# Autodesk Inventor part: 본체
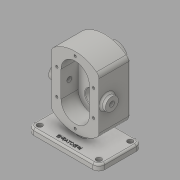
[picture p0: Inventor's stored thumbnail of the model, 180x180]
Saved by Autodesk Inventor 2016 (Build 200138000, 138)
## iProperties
Created: 2019-03
Part Number: 본체
Material: Generic
Document SubType Name: Modeling
Designer: Administrator
Density: 1 g/cm^3
Appearance: Default
Author: Administrator
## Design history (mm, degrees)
sketch "스케치1"
  geometry: L1 (60, -36.5)-(-60, -36.5); L2 (-60, -36.5)-(-60, 36.5); L3 (-60, 36.5)-(60, 36.5); L4 (60, 36.5)-(60, -36.5); L5 (60, -36.5)-(-60, 36.5); L6 (-60, -36.5)-(60, 36.5); 1 further point
  constraints: 12 end point, 2 midpoint, 2 parallel, 1 horizontal, 1 perpendicular
  dimensions: "d0" = 120 distance of L1.start L1.end; "d1" = 73 distance of L1.end L2.end
extrude "돌출1" new body sketch "스케치1" distance "d2" = 10; taper "d3" = 0 deg
fillet "모깎기1" dims "d4" = 10
sketch "스케치2"
  geometry: 1 further point
sketch "스케치3"
  geometry: L1 (50, 36.5)-(-50, 36.5) reference; L2 (0, 0)-(0, 36.5); L3 (-6, -6.5)-(6, -6.5); L4 (6, -6.5)-(6, 36.5); L5 (6, 36.5)-(-6, 36.5); L6 (-6, 36.5)-(-6, -6.5); 1 further point
  constraints: 10 end point, 3 midpoint, 2 parallel, 1 horizontal, 1 perpendicular
  dimensions: "d42" = 12 distance of L3.start L3.end; "d43" = 43 distance of L3.end L4.end
extrude "돌출2" join sketch "스케치3" distance "d44" = 78; taper "d45" = 0 deg
fillet "모깎기3" dims "d46" = 3
sketch "스케치4"
  geometry: L1 (10, 66)-(90, 66); L2 (90, 66)-(90, 110); L3 (90, 110)-(10, 110); L4 (10, 110)-(10, 66); L5 (56, 88)-(44, 88) reference; L6 (10, 66)-(90, 110); L7 (90, 66)-(10, 110); L8 (50, 0)-(50, 138); L9 (50, 138)-(61.235, 138); L10 (10, 110)-(10, 122.721); L11 (90, 110)-(90, 122.721); L12 (10, 66)-(-38.552, 66); L13 (90, 66)-(122.984, 66); A1 r 60 centre (50, 78) between (90, 122.721) and (10, 122.721); 1 further point
  constraints: 24 end point, 4 horizontal, 3 midpoint, 3 point on circle, 3 vertical, 2 parallel, 1 centre point, 1 perpendicular, 1 point on line, 1 tangent
  dimensions: "d47" = 44 distance of L1.end L2.end; "d48" = 80 distance of L2.end L3.end; "d49" = 138 distance of L8.start L8.end; "d51" = 60 radius of A1
extrude "돌출3" join sketch "스케치4" distance "d52" = 53; taper "d53" = 0 deg
node "작업 평면1"
sketch "스케치7"
  geometry: L1 (-50, 100)-(-50, 56); L2 (-50, 100)-(-50, 56); L3 (-74, 100)-(-74, 56); L4 (-26, 56)-(-26, 100); A1 r 60 centre (-50, 78) between (-10, 122.721) and (-90, 122.721) reference; A2 r 24 centre (-50, 100) between (-26, 100) and (-74, 100); A3 r 24 centre (-50, 56) between (-74, 56) and (-26, 56); 3 further points
  constraints: 10 end point, 4 point on circle, 4 tangent, 2 centre point, 2 midpoint, 2 vertical, 1 coincident, 1 parallel
  dimensions: "d55" = 44 distance of L1.start L1.end; "d56" = 24 radius of A2
extrude "돌출4" cut sketch "스케치7" distance "d57" = 29; taper "d58" = 0 deg
fillet "모깎기4" dims "d59" = 10
sketch "스케치8"
  geometry: L1 (90, 38)-(90, 118) reference; L2 (10, 38)-(10, 118) reference; L3 (44, 7)-(44, 18.301) reference; L4 (0, 7)-(44, 7) reference; L5 (0, 0)-(0, 7) reference; L6 (100, 0)-(0, 0) reference; L7 (100, 7)-(100, 0) reference; L8 (56, 7)-(100, 7) reference; L9 (56, 18.301)-(56, 7) reference; C1 r 19 at (50, 100); A1 r 10 centre (80, 38) between (86, 30) and (90, 38) reference; A2 r 10 centre (80, 118) between (90, 118) and (86, 126) reference; A3 r 60 centre (50, 78) between (86, 126) and (14, 126) reference; A4 r 10 centre (20, 118) between (14, 126) and (10, 118) reference; A5 r 10 centre (20, 38) between (10, 38) and (14, 30) reference; A6 r 60 centre (50, 78) between (14, 30) and (44, 18.301) reference; A7 r 60 centre (50, 78) between (56, 18.301) and (86, 30) reference; A8 r 24 centre (50, 100) between (74, 100) and (26, 100) reference; 1 further point
  constraints: 1 centre point, 1 coincident
  dimensions: "d60" = 38 diameter of C1
extrude "돌출5" join sketch "스케치8" distance "d61" = 17; taper "d62" = 0 deg
fillet "모깎기5" dims "d63" = 3
hole "구멍5" diameter "d66" = 17; stored, may be unused: countersink angle "d70" = 90 deg, drill point angle "d72" = 118 deg; dims "d64" = 10, "d65" = 10, "d67" = 6, "d68" = 28, "d69" = 7.3, "d71" = 8
fillet "모깎기6" dims "d73" = 0.5
sketch "스케치9"
  geometry: L1 (114, -52.8)-(114.404, -53.5); L2 (81, -53.5)-(119, -53.5) reference; L3 (114, -46.7)-(114, -53.5) reference; L4 (114.404, -53.5)-(114, -53.5); L5 (114, -53.5)-(114, -52.8); L6 (91.5, -46.2)-(108.5, -46.2) reference; L7 (100, -46.2)-(100, -61.618); 1 further point
  constraints: 8 end point, 2 collinear, 1 midpoint, 1 point on line, 1 vertical
  dimensions: "d74" = 0.7 distance from line of L2 L1.start; "d75" = 30 deg angle of L3 L1
revolve "회전1" sketch "스케치9" stored, may be unused: angle "d76" = 90 deg
hole "구멍6" diameter "d79" = 25; stored, may be unused: countersink angle "d83" = 90 deg, drill point angle "d85" = 0 deg; dims "d77" = 10, "d78" = 10, "d80" = 6, "d81" = 28, "d82" = 7.3, "d84" = 15
hole "구멍7" diameter "d88" = 25; stored, may be unused: countersink angle "d92" = 90 deg, drill point angle "d94" = 0 deg; dims "d86" = 10, "d87" = 10, "d89" = 6, "d90" = 28, "d91" = 7.3, "d93" = 15
sketch "스케치11"
  geometry: L1 (-53, 80)-(-53, 0) reference; L2 (-53, 40)-(-39, 40); L3 (-10, -38)-(-63, -38) reference; C1 r 11 at (-39, 40); 1 further point
  constraints: 2 end point, 1 centre point, 1 coincident, 1 horizontal, 1 midpoint
  dimensions: "d95" = 14 distance of L2.start L2.end; "d96" = 78 distance between parallel lines of L3 L2; "d97" = 22 diameter of C1
extrude "돌출6" join sketch "스케치11" distance "d98" = 8; taper "d99" = 0 deg
fillet "모깎기7" dims "d100" = 3
fillet "모깎기8" dims "d101" = 3
hole "구멍8" diameter "d104" = 8.376; stored, may be unused: countersink angle "d108" = 90 deg, drill point angle "d110" = 0 deg; dims "d105" = 20, "d106" = 28, "d107" = 7.3, "d109" = 27.3, "d130" = 10, "d131" = 10
chamfer "모따기1" distance "d111" = 1; stored, may be unused: second distance "d112" = 2, angle "d113" = 45 deg
fillet "모깎기9" dims "d114" = 3
fillet "모깎기10" dims "d115" = 3
sketch "스케치13"
  geometry: L1 (-90, 78)-(-10, 78); L2 (-50, 56)-(-50, 100); L3 (-19, 56)-(-19, 100); L4 (-81, 100)-(-81, 56); L5 (-50, 78)-(-50, 100); L6 (-50, 100)-(-19, 100); L7 (-50, 100)-(-81, 100); L8 (-50, 100)-(-50, 131); L9 (-90, 118)-(-90, 78) reference; L10 (-10, 118)-(-10, 78) reference; L11 (0, 0)-(-100, 0) reference; C1 r 13.5 at (-50, 100) reference; A1 r 31 centre (-50, 56) between (-81, 56) and (-19, 56); A2 r 31 centre (-50, 100) between (-19, 100) and (-81, 100); 1 further point
  constraints: 18 end point, 5 point on circle, 4 tangent, 2 centre point, 2 midpoint, 1 parallel, 1 point on line, 1 vertical
  dimensions: "d116" = 31 radius of A2; "d117" = 22 distance of L5.start L5.end; "d125" = 78 distance between parallel lines of L11 L1
hole "구멍9" sketch "스케치13" at (-50, 131), (-81, 100), (-19, 100) diameter "d118" = 4.134; stored, may be unused: countersink angle "d122" = 90 deg, drill point angle "d124" = 118 deg; dims "d119" = 10, "d120" = 28, "d121" = 7.3, "d123" = 12
sketch "스케치14"
  geometry: L1 (-50, -36.5)-(50, -36.5) reference; L2 (-60, 26.5)-(-60, -26.5) reference; 2 further points
  constraints: 1 other
  dimensions: "d126" = 10 distance from line of L1 point (0, -26.5); "d127" = 60 distance from line of L2 point (0, -26.5)
feature "엠보싱1" sketch "스케치14" dims "d43" = 43, "d128" = 0.5, "d129" = 0
hole "구멍10" diameter "d134" = 9; stored, may be unused: countersink angle "d138" = 90 deg, drill point angle "d140" = 118 deg; dims "d132" = 10, "d133" = 10, "d135" = 10, "d136" = 28, "d137" = 7.3, "d139" = 12
hole "구멍11" diameter "d143" = 9; stored, may be unused: countersink angle "d147" = 90 deg, drill point angle "d149" = 118 deg; dims "d141" = 10, "d142" = 10, "d144" = 10, "d145" = 28, "d146" = 7.3, "d148" = 12
hole "구멍12" diameter "d152" = 9; stored, may be unused: countersink angle "d156" = 90 deg, drill point angle "d158" = 118 deg; dims "d150" = 10, "d151" = 10, "d153" = 10, "d154" = 28, "d155" = 7.3, "d157" = 12
hole "구멍13" diameter "d161" = 9; stored, may be unused: countersink angle "d165" = 90 deg, drill point angle "d167" = 118 deg; dims "d159" = 10, "d160" = 10, "d162" = 10, "d163" = 28, "d164" = 7.3, "d166" = 12
node "솔리드1"
mirror "대칭1"
mirror "대칭2"
mirror "대칭3"
node "투영된 루프1"
other parameters: "d54" = 78
